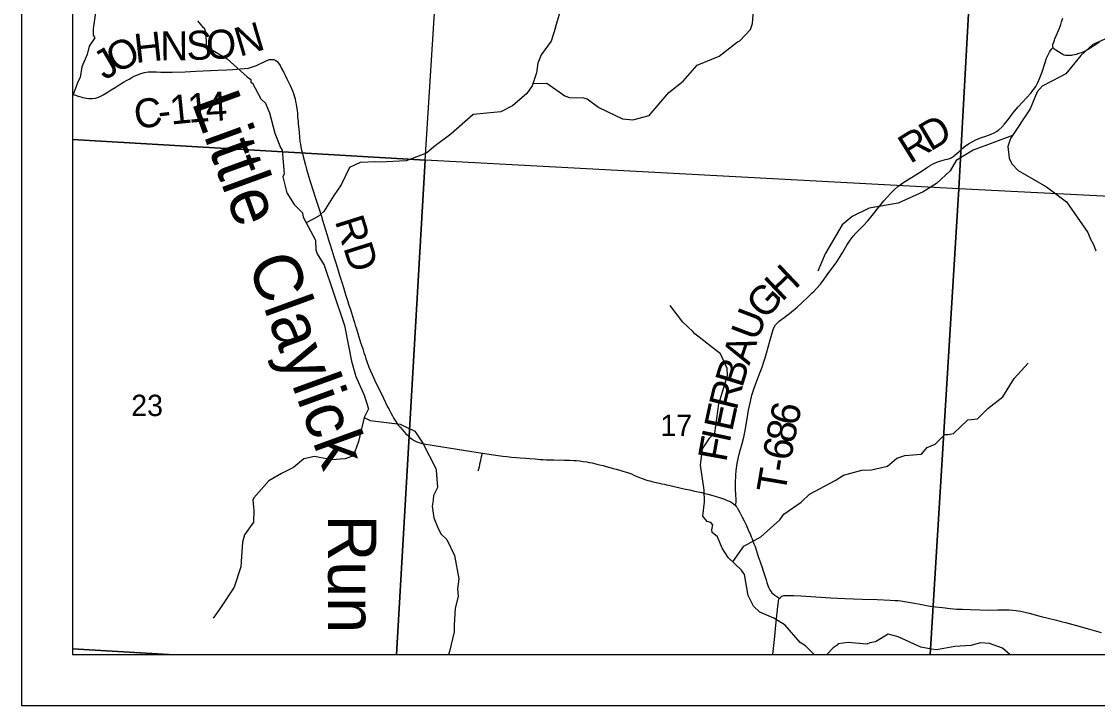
# Model space of a CAD drawing. Extents: x 0 to 34, y 0 to 22.
# Drawn here: x 2 to 4.109, y 14 to 15.341 of the extents above; entities that cross this region are included whole.
import ezdxf

# ---------------------------------------------------------------- set-up
doc = ezdxf.new("R2010")
doc.units = 0
for name, color, linetype in [('Default', 7, 'Continuous'), ('GM_X_County_Road', 7, 'Continuous'), ('GM_X_County_Road_Text', 7, 'Continuous'), ('GM_X_Minor_River', 7, 'Continuous'), ('GM_X_Minor_River_Text', 7, 'Continuous'), ('GM_X_Section', 7, 'Continuous'), ('GM_X_Section_Text', 7, 'Continuous'), ('GM_X_Township_Road', 7, 'Continuous'), ('GM_X_Township_Road_Text', 7, 'Continuous'), ('SH_Data', 7, 'Continuous'), ('SH_Text', 7, 'Continuous')]:
    doc.layers.add(name, color=color, linetype=linetype)

msp = doc.modelspace()

# ---------------------------------------------------------------- linework, layer by layer
at = {"layer": 'Default'}
for points in [[(2.1, 16.1254), (2.1, 15.1095), (2.7909, 15.0689), (2.8549, 16.0795)], [(2.1, 16.1239), (2.1, 14.1), (4.8164, 14.1), (4.8734, 15.0246), (4.8987, 15.3279), (4.9458, 15.9099), (4.9525, 15.9829), (4.6644, 15.9921), (3.9292, 16.0191), (3.6368, 16.0331), (2.1721, 16.1195)], [(2.1, 15.1095), (2.1, 14.1111), (2.2886, 14.1), (2.7351, 14.1), (2.7909, 15.0689)], [(2.7351, 14.1), (3.7808, 14.1), (3.8368, 15.0128), (2.7909, 15.0689)], [(3.7808, 14.1), (4.8257, 14.1), (4.8777, 14.9601), (3.8368, 15.0128)], [(2.1, 14.1111), (2.1, 14.1), (2.2886, 14.1)]]:
    msp.add_lwpolyline(points, close=True, dxfattribs=at)
at = {"layer": 'GM_X_County_Road'}
for points in [[(2.1, 15.1984), (2.1056, 15.1964), (2.1113, 15.1945), (2.1163, 15.1929), (2.1197, 15.192), (2.1236, 15.191), (2.1271, 15.1905), (2.1317, 15.1899), (2.1386, 15.1897), (2.1449, 15.1905), (2.1492, 15.1918), (2.1539, 15.1936), (2.16, 15.1968), (2.1677, 15.2016), (2.1756, 15.2065), (2.1835, 15.2114), (2.1915, 15.2164), (2.2001, 15.2217), (2.2058, 15.225), (2.211, 15.2279), (2.2163, 15.2309), (2.221, 15.2333), (2.2257, 15.2357), (2.2336, 15.2389), (2.2413, 15.241), (2.2485, 15.2419), (2.2546, 15.2421), (2.2645, 15.2418), (2.2732, 15.2416), (2.28, 15.2416), (2.2862, 15.2416), (2.295, 15.2417), (2.321, 15.2424), (2.3415, 15.2432), (2.385, 15.2453), (2.4024, 15.2461), (2.414, 15.2467), (2.4222, 15.2472), (2.4284, 15.2477), (2.4373, 15.2485), (2.4446, 15.2495), (2.4507, 15.2511), (2.4566, 15.2531), (2.4607, 15.2548), (2.4659, 15.2569), (2.4717, 15.2598), (2.4772, 15.2625), (2.4809, 15.2643), (2.486, 15.2661), (2.4906, 15.2666), (2.4946, 15.266), (2.4983, 15.2642), (2.5011, 15.2621), (2.5039, 15.2589), (2.5069, 15.2543), (2.5098, 15.2488), (2.5141, 15.2407), (2.5171, 15.2345), (2.5202, 15.2282), (2.5234, 15.2217), (2.5265, 15.2152), (2.5293, 15.2094), (2.5311, 15.2049), (2.5331, 15.1997), (2.5344, 15.1951), (2.5362, 15.189), (2.5372, 15.1842), (2.5384, 15.1787), (2.5391, 15.1734), (2.5401, 15.1665), (2.5406, 15.1611), (2.5412, 15.1533), (2.542, 15.1449), (2.5424, 15.1395), (2.5432, 15.1306), (2.5439, 15.1225), (2.5447, 15.1146), (2.5457, 15.1058), (2.5466, 15.1003), (2.5484, 15.0911), (2.55, 15.0844), (2.552, 15.076), (2.5539, 15.0688), (2.5565, 15.0591), (2.5587, 15.0514), (2.565, 15.0292), (2.5721, 15.0067), (2.5755, 14.9967), (2.5783, 14.9884), (2.5808, 14.9808), (2.5845, 14.9693), (2.5861, 14.9642), (2.5878, 14.9589), (2.5895, 14.9533), (2.5928, 14.9427), (2.596, 14.9322), (2.599, 14.9221), (2.6019, 14.9125), (2.6049, 14.903), (2.6082, 14.8925), (2.6124, 14.8792), (2.6153, 14.8698), (2.6193, 14.8571), (2.6235, 14.8438), (2.6279, 14.8295), (2.6311, 14.8193), (2.6353, 14.8055), (2.6389, 14.7939), (2.6417, 14.785), (2.6438, 14.7784), (2.6466, 14.7696), (2.6486, 14.7632), (2.6512, 14.7547), (2.6523, 14.751), (2.654, 14.7458), (2.6558, 14.7401), (2.6647, 14.7114), (2.6665, 14.706), (2.6688, 14.6988), (2.6712, 14.6914), (2.6732, 14.6855), (2.6751, 14.6795), (2.6763, 14.6762), (2.6777, 14.6722), (2.6795, 14.6673), (2.681, 14.6631), (2.6839, 14.6562), (2.687, 14.6487), (2.6898, 14.6428), (2.6938, 14.6341), (2.6995, 14.6224), (2.7093, 14.6022), (2.7175, 14.5855), (2.7204, 14.58), (2.7238, 14.5736), (2.727, 14.5675), (2.7298, 14.5627), (2.7324, 14.5584), (2.7358, 14.5532), (2.7378, 14.5507)], [(2.7378, 14.5507), (2.7391, 14.549), (2.742, 14.5453), (2.7464, 14.5401), (2.7497, 14.5365), (2.7535, 14.5322), (2.7562, 14.5296), (2.7609, 14.5254), (2.7655, 14.5222), (2.7698, 14.5194), (2.7749, 14.5169), (2.7785, 14.5156), (2.7833, 14.5141), (2.7918, 14.5123), (2.8008, 14.5108), (2.809, 14.5094), (2.8501, 14.5029), (2.8704, 14.4997), (2.9032, 14.4946), (2.925, 14.4914), (2.9345, 14.4899), (2.9433, 14.4888), (2.9512, 14.4878), (2.9601, 14.487), (2.9704, 14.486), (2.9775, 14.4855), (2.9892, 14.4845), (2.9964, 14.4839), (3.0067, 14.4832), (3.0156, 14.4825), (3.0223, 14.4822), (3.0292, 14.4818), (3.0346, 14.4817), (3.0432, 14.4815), (3.064, 14.481), (3.0739, 14.4808), (3.0825, 14.4803), (3.0873, 14.48), (3.0942, 14.4795), (3.1011, 14.4785), (3.1077, 14.4775), (3.1128, 14.4765), (3.1186, 14.4754), (3.1277, 14.4732), (3.133, 14.4719), (3.1398, 14.4701), (3.1456, 14.4686), (3.153, 14.4665), (3.1599, 14.4646), (3.1655, 14.4631), (3.1729, 14.461), (3.1788, 14.4594), (3.1831, 14.4582), (3.1878, 14.4566), (3.1917, 14.4552), (3.1953, 14.4538), (3.2004, 14.4517), (3.2078, 14.4485), (3.2147, 14.4457), (3.2204, 14.4437), (3.2252, 14.442), (3.2314, 14.4402), (3.2353, 14.4392), (3.2405, 14.438), (3.2472, 14.4365), (3.2522, 14.4354), (3.2552, 14.4348), (3.2599, 14.4338), (3.264, 14.4327), (3.2682, 14.4318), (3.2742, 14.4304), (3.2928, 14.4262), (3.3012, 14.4243), (3.3097, 14.4225), (3.3166, 14.4209), (3.323, 14.4195), (3.3331, 14.4172), (3.3392, 14.4158), (3.3457, 14.4142), (3.3523, 14.4125), (3.3594, 14.4105), (3.3717, 14.4065), (3.3778, 14.4043), (3.3833, 14.4021), (3.3868, 14.4005), (3.39, 14.3989), (3.393, 14.3971), (3.3955, 14.3954), (3.3978, 14.3935), (3.3991, 14.3922), (3.4009, 14.3901), (3.4026, 14.3878), (3.4041, 14.3853), (3.4071, 14.3799), (3.4127, 14.3692), (3.4161, 14.362), (3.4202, 14.3539), (3.4241, 14.3445), (3.4288, 14.3342), (3.4302, 14.3305), (3.4319, 14.3264), (3.4335, 14.3224), (3.4356, 14.3167), (3.4376, 14.3114), (3.4441, 14.2922), (3.4477, 14.2817), (3.4516, 14.2703), (3.453, 14.2662), (3.4551, 14.2597), (3.4579, 14.2503), (3.4592, 14.2461), (3.4609, 14.241), (3.463, 14.2349), (3.4642, 14.2319), (3.4652, 14.2293), (3.4668, 14.2266), (3.4679, 14.2247), (3.4693, 14.2229), (3.4707, 14.2211), (3.4731, 14.2189), (3.4767, 14.2162), (3.4846, 14.2109), (3.4858, 14.2101)], [(3.4858, 14.2101), (3.4873, 14.2119), (3.4886, 14.213), (3.4902, 14.214), (3.4921, 14.2148), (3.494, 14.2153), (3.4962, 14.2156), (3.4989, 14.2158), (3.5025, 14.2159), (3.5138, 14.2155), (3.5276, 14.2147), (3.5565, 14.2129), (3.5859, 14.2112), (3.6139, 14.2099), (3.6473, 14.2086), (3.677, 14.2077), (3.7025, 14.2067), (3.7124, 14.2061), (3.7179, 14.2058), (3.7234, 14.2052), (3.7345, 14.2035), (3.7503, 14.2006), (3.7644, 14.1978), (3.7772, 14.1956), (3.7915, 14.1936), (3.8053, 14.1919), (3.8202, 14.1902), (3.8267, 14.1896), (3.8328, 14.1891), (3.844, 14.1885), (3.8595, 14.1879), (3.8781, 14.1873), (3.8968, 14.187), (3.9135, 14.1873), (3.9257, 14.1875), (3.936, 14.1872), (3.9432, 14.1869), (3.9494, 14.1864), (3.9536, 14.1858), (3.9584, 14.1849), (3.9749, 14.181), (3.9982, 14.1747), (4.0119, 14.1713), (4.0285, 14.1672), (4.0376, 14.1649), (4.0464, 14.1625), (4.0679, 14.1565), (4.0929, 14.1495), (4.1159, 14.1431)], [(3.4727, 14.1), (3.4763, 14.1352), (3.4787, 14.1575), (3.4811, 14.1816), (3.4822, 14.1938), (3.4834, 14.2034), (3.4839, 14.2057), (3.4844, 14.2075), (3.4852, 14.2092), (3.4858, 14.2101)]]:
    msp.add_lwpolyline(points, dxfattribs=at)
at = {"layer": 'GM_X_Minor_River'}
for points in [[(3.4329, 15.3367), (3.4351, 15.3702), (3.4525, 15.3942), (3.4647, 15.4288), (3.4749, 15.4801), (3.467, 15.5204), (3.4651, 15.5505), (3.4856, 15.5893), (3.4901, 15.6049), (3.4909, 15.6269), (3.4973, 15.6326), (3.5072, 15.6528), (3.5068, 15.6916), (3.4936, 15.7687), (3.4876, 15.8007)], [(3.0463, 15.3291), (3.0628, 15.3843)], [(2.1467, 15.3721), (2.1404, 15.3265), (2.1404, 15.314), (2.1435, 15.309), (2.1329, 15.2923), (2.1287, 15.2759), (2.1182, 15.2519), (2.1148, 15.2307), (2.111, 15.2238), (2.1, 15.1941)], [(2.3448, 15.3418), (2.3547, 15.3301), (2.3581, 15.3282), (2.3612, 15.3183), (2.3616, 15.2944), (2.3676, 15.2883), (2.4032, 15.2675), (2.4425, 15.2322), (2.4493, 15.2269), (2.4493, 15.222), (2.4528, 15.2201), (2.469, 15.1893), (2.4781, 15.1806), (2.4842, 15.1662), (2.4861, 15.1616), (2.4963, 15.1217), (2.5077, 15.0936), (2.5111, 15.0883), (2.5145, 15.042), (2.5119, 15.0363), (2.5145, 15.026), (2.5202, 15.0051), (2.5346, 14.9823), (2.5505, 14.9657), (2.552, 14.9573), (2.5759, 14.9121), (2.5767, 14.8931), (2.5793, 14.8851), (2.593, 14.8631), (2.6111, 14.8107), (2.6331, 14.7446), (2.6468, 14.6751), (2.6552, 14.6447), (2.6718, 14.6083), (2.6802, 14.5817), (2.6715, 14.5642), (2.6832, 14.5585), (2.7422, 14.5514), (2.7706, 14.5378), (2.7864, 14.5143), (2.8118, 14.4645), (2.8126, 14.4615), (2.8156, 14.4273), (2.8077, 14.4113), (2.8066, 14.4026), (2.8047, 14.3908), (2.8081, 14.368), (2.8169, 14.3471), (2.8225, 14.3357), (2.8339, 14.3255), (2.8487, 14.294), (2.857, 14.2484), (2.8544, 14.2286), (2.8559, 14.2138), (2.8499, 14.191), (2.8477, 14.1575), (2.848, 14.1548), (2.848, 14.1446), (2.8386, 14.1058), (2.8368, 14.1)], [(3.0023, 15.219), (3.0293, 15.2199), (3.0649, 15.1949), (3.0738, 15.1919), (3.1014, 15.1914), (3.1085, 15.1893), (3.1315, 15.1722), (3.1777, 15.1499), (3.198, 15.1477), (3.2304, 15.1565), (3.2684, 15.2013), (3.2967, 15.2239), (3.3241, 15.2553), (3.3673, 15.2725), (3.4034, 15.301), (3.408, 15.3031), (3.4287, 15.3249), (3.4329, 15.3368)], [(4.1959, 15.3376), (4.1676, 15.326), (4.0999, 15.2957), (4.0761, 15.2743), (4.0471, 15.2385), (4.0354, 15.2323), (4.0002, 15.2143), (3.9908, 15.2032), (3.9769, 15.1698), (3.9382, 15.1115), (3.933, 15.0955), (3.9354, 15.0727), (3.9408, 15.0617), (3.9534, 15.0489), (4.0086, 15.0165), (4.0479, 14.9871), (4.0896, 14.9273), (4.095, 14.9144), (4.1008, 14.9038), (4.1058, 14.8913)], [(3.0463, 15.3291), (3.0383, 15.3024), (3.0185, 15.2753), (3.012, 15.2588), (3.0092, 15.2399), (3.0008, 15.2144), (2.9902, 15.1995), (2.9622, 15.1753), (2.9396, 15.1639), (2.9255, 15.1621), (2.8853, 15.1584), (2.8415, 15.1196), (2.8082, 15.0948), (2.7938, 15.0824), (2.7537, 15.0677), (2.7022, 15.0648), (2.6943, 15.0654), (2.664, 15.0645), (2.6426, 15.0545), (2.6264, 15.0205), (2.6122, 14.9997), (2.5927, 14.9684), (2.5811, 14.9585), (2.5577, 14.9464)], [(3.9422, 15.1175), (3.8651, 15.0883), (3.8318, 15.068), (3.8202, 15.0478), (3.793, 15.023), (3.7673, 15.0069), (3.7181, 14.9846), (3.6616, 14.9749), (3.6283, 14.9584), (3.6083, 14.9419), (3.5752, 14.8856), (3.561, 14.8513)], [(3.5535, 14.1), (3.5364, 14.1169), (3.526, 14.1233), (3.4965, 14.1577), (3.4746, 14.1709), (3.4473, 14.1832), (3.4348, 14.1946), (3.4241, 14.2158), (3.4167, 14.2567), (3.4113, 14.2652), (3.3848, 14.2904), (3.3729, 14.3086), (3.3641, 14.3305), (3.3538, 14.3392), (3.3528, 14.3445), (3.355, 14.3543), (3.351, 14.359), (3.3435, 14.3604), (3.3351, 14.3709), (3.3386, 14.3989), (3.3378, 14.4221), (3.331, 14.4713), (3.3346, 14.5031), (3.3492, 14.5246), (3.3586, 14.5338), (3.3667, 14.5913), (3.3835, 14.6466), (3.3828, 14.6607), (3.3701, 14.6892), (3.3199, 14.7284), (3.3155, 14.7331), (3.296, 14.7515), (3.2716, 14.7838)], [(3.3944, 14.2813), (3.4157, 14.3121), (3.4488, 14.3308), (3.4861, 14.3638), (3.4944, 14.375), (3.5283, 14.3986), (3.5447, 14.4144), (3.5946, 14.4412), (3.6112, 14.4517), (3.6467, 14.4616), (3.666, 14.4621), (3.6975, 14.4691), (3.7158, 14.4845), (3.7314, 14.4897), (3.764, 14.4924), (3.775, 14.5057), (3.7907, 14.5121), (3.8094, 14.5312), (3.8162, 14.5314), (3.8269, 14.5329), (3.8549, 14.5598), (3.8739, 14.5618), (3.8938, 14.5824), (3.9232, 14.605), (3.9458, 14.6412), (3.9728, 14.6711)], [(2.6715, 14.5642), (2.6603, 14.5174), (2.6541, 14.499), (2.6466, 14.4882), (2.6343, 14.4833), (2.6078, 14.4815), (2.574, 14.4882), (2.5531, 14.4836), (2.5333, 14.4668), (2.5095, 14.455), (2.4848, 14.4402), (2.4551, 14.4073), (2.4531, 14.4025), (2.4551, 14.3819), (2.4544, 14.3595), (2.437, 14.3346), (2.4328, 14.32), (2.4305, 14.2824), (2.4298, 14.2718), (2.4169, 14.232), (2.39, 14.1911), (2.3758, 14.171)], [(3.9373, 14.1), (3.9224, 14.1125), (3.8971, 14.1216), (3.8793, 14.1227), (3.8608, 14.1177), (3.8294, 14.1153), (3.7935, 14.1088), (3.7837, 14.1103), (3.7629, 14.1144), (3.7183, 14.1345), (3.6986, 14.1401), (3.6737, 14.1245), (3.6627, 14.1225), (3.657, 14.1199), (3.6204, 14.1232), (3.6007, 14.1209), (3.5984, 14.1182), (3.5905, 14.1133), (3.5785, 14.1)]]:
    msp.add_lwpolyline(points, dxfattribs=at)
at = {"layer": 'GM_X_Section'}
for points in [[(2.8549, 16.0795), (3.8924, 16.0203), (3.8368, 15.0128), (2.7909, 15.0689)], [(3.8924, 16.0203), (4.9447, 15.9846), (4.9568, 15.9843), (4.8777, 14.9601), (3.8368, 15.0128)]]:
    msp.add_lwpolyline(points, close=True, dxfattribs=at)
at = {"layer": 'GM_X_Township_Road'}
for points in [[(4.1125, 15.3002), (4.0925, 15.2869), (4.0848, 15.2828), (4.0773, 15.2796), (4.0723, 15.278), (4.0673, 15.2763), (4.0636, 15.2754), (4.0606, 15.2747), (4.0576, 15.2742), (4.0544, 15.2738), (4.0494, 15.2738), (4.0462, 15.2743), (4.0437, 15.2749), (4.0409, 15.2761), (4.027, 15.2845), (4.0249, 15.286), (4.0233, 15.2874), (4.0224, 15.2885), (4.0218, 15.2896), (4.0213, 15.2911), (4.0213, 15.293), (4.0214, 15.2949), (4.0216, 15.2967), (4.0223, 15.2986), (4.0245, 15.3042), (4.0255, 15.3067), (4.0281, 15.3126), (4.0307, 15.3187), (4.0341, 15.3278), (4.0367, 15.3349), (4.0385, 15.3404), (4.0408, 15.3473)], [(3.3991, 14.3922), (3.4003, 14.3956), (3.4007, 14.3978), (3.4009, 14.4001), (3.4009, 14.4028), (3.3993, 14.4241), (3.3991, 14.4301), (3.3992, 14.4361), (3.4001, 14.4515), (3.4009, 14.4607), (3.4027, 14.4742), (3.405, 14.487), (3.4076, 14.4978), (3.4121, 14.5133), (3.4155, 14.526), (3.4181, 14.5388), (3.4223, 14.562), (3.4251, 14.5786), (3.4287, 14.5962), (3.4316, 14.6083), (3.4351, 14.6201), (3.4389, 14.6312), (3.4478, 14.6536), (3.4515, 14.6635), (3.455, 14.6735), (3.4576, 14.6818), (3.4602, 14.6907), (3.4635, 14.7027), (3.4666, 14.714), (3.4703, 14.7278), (3.4732, 14.7367), (3.4754, 14.7417), (3.478, 14.7459), (3.4815, 14.7501), (3.4851, 14.7535), (3.4976, 14.7626), (3.5054, 14.7687), (3.5202, 14.7811), (3.5308, 14.7907), (3.5407, 14.8), (3.5496, 14.8086), (3.553, 14.8118), (3.5582, 14.8171), (3.5658, 14.826), (3.573, 14.8354), (3.5791, 14.8441), (3.5865, 14.8541), (3.5906, 14.8596), (3.598, 14.8696), (3.6015, 14.8747), (3.6048, 14.88), (3.6098, 14.8886), (3.6178, 14.9026), (3.6243, 14.9124), (3.6298, 14.9199), (3.6351, 14.9259), (3.6494, 14.9404), (3.6588, 14.9503), (3.6673, 14.9602), (3.6823, 14.9792), (3.6904, 14.9893), (3.6973, 14.9973), (3.7032, 15.0036), (3.7111, 15.0115), (3.7175, 15.0174), (3.7218, 15.0208), (3.7274, 15.0247), (3.7495, 15.0382), (3.7652, 15.0482), (3.7734, 15.0537), (3.7796, 15.0577), (3.7866, 15.0616), (3.7939, 15.0649), (3.8021, 15.0678), (3.811, 15.0701), (3.8177, 15.0718), (3.8218, 15.0736), (3.826, 15.0762), (3.829, 15.0785), (3.8332, 15.082), (3.837, 15.0855), (3.8437, 15.0915), (3.8498, 15.0964), (3.8563, 15.1009), (3.8631, 15.1051), (3.8702, 15.1088), (3.8794, 15.1125), (3.8899, 15.1163), (3.9004, 15.1199), (3.9062, 15.1224), (3.911, 15.1252), (3.9156, 15.1284), (3.9211, 15.1334), (3.9265, 15.1394), (3.9342, 15.1491), (3.9432, 15.1609), (3.9535, 15.1733), (3.9627, 15.1833), (3.9699, 15.191), (3.9782, 15.2003), (3.9836, 15.2072), (3.9877, 15.2134), (3.9919, 15.2211), (3.9959, 15.2302), (4.0004, 15.2418), (4.0061, 15.2602), (4.0091, 15.269), (4.0125, 15.2769), (4.0145, 15.2806), (4.0166, 15.2842), (4.0193, 15.2873), (4.0218, 15.2896)], [(2.8953, 14.4597), (2.8973, 14.4676), (2.8981, 14.4715), (2.8992, 14.4764), (2.8999, 14.48), (2.9009, 14.4843), (2.9018, 14.4882), (2.9032, 14.4946)]]:
    msp.add_lwpolyline(points, dxfattribs=at)
at = {"layer": 'SH_Data'}
for p, q in [((2, 21), (2, 14)), ((2.1, 20.9), (2.1, 14.1)), ((2.1, 14.1), (8.9, 14.1)), ((2.1, 14.1), (2.1, 14.1)), ((2, 14), (9, 14))]:
    msp.add_line(p, q, dxfattribs=at)
at = {"layer": 'SH_Text'}
msp.add_lwpolyline([(2.1, 20.9), (2.1, 14.1), (8.0885, 14.1)], dxfattribs=at)

# ---------------------------------------------------------------- texts
at = {"layer": 'GM_X_County_Road_Text'}
for s, height, rotation, p in [('N', 0.0568, 16.5268, (2.4276, 15.2714)), ('H', 0.0568, 6.267, (2.2239, 15.2592)), ('N', 0.0568, 0.3752, (2.2721, 15.2646)), ('S', 0.0568, 2.2013, (2.3241, 15.265)), ('O', 0.0568, 2.752, (2.363, 15.2665)), ('J', 0.0568, 30.3125, (2.1625, 15.2247)), ('O', 0.0568, 27.4823, (2.1849, 15.2378)), ('C', 0.0568, 7.1216, (2.224, 15.1301)), ('1', 0.0568, 5.7209, (2.2931, 15.1386)), ('1', 0.0568, 4.7515, (2.3277, 15.1421)), ('4', 0.0568, 3.3897, (2.3622, 15.1449)), ('-', 0.0568, 6.6893, (2.2702, 15.1359)), ('RD', 0.05682, 287.5008, (2.6138, 14.9498))]:
    msp.add_text(s, height=height, rotation=rotation, dxfattribs=at).set_placement(p)
at = {"layer": 'GM_X_Minor_River_Text'}
for s, rotation, p in [('Little', 289.9986, (2.3329, 15.1833)), ('Claylick', 289.9986, (2.4426, 14.8677)), ('Run', 269.9991, (2.601, 14.3742))]:
    msp.add_text(s, height=0.0947, rotation=rotation, dxfattribs=at).set_placement(p)
at = {"layer": 'GM_X_Section_Text'}
for s, p in [('23', (2.215, 14.5673)), ('17', (3.2521, 14.5282))]:
    msp.add_text(s, height=0.04186, rotation=0, dxfattribs=at).set_placement(p)
at = {"layer": 'GM_X_Township_Road_Text'}
for s, rotation, p in [('D', 30.5858, (3.7811, 15.0854)), ('R', 31.935, (3.7418, 15.0609)), ('H', 43.4942, (3.4902, 14.7902)), ('G', 47.346, (3.457, 14.7542)), ('U', 69.0963, (3.4421, 14.7123)), ('A', 71.307, (3.4263, 14.6655)), ('B', 72.6895, (3.4125, 14.6213)), ('R', 76.1223, (3.4016, 14.5768)), ('E', 77.7836, (3.3927, 14.5357)), ('6', 78.0221, (3.521, 14.5463)), ('8', 78.5482, (3.514, 14.5122)), ('I', 77.9606, (3.3878, 14.513)), ('F', 79.6956, (3.3811, 14.4757)), ('6', 79.2004, (3.5075, 14.4779)), ('T', 80.3939, (3.4964, 14.4134)), ('-', 79.9493, (3.5035, 14.4552))]:
    msp.add_text(s, height=0.0568, rotation=rotation, dxfattribs=at).set_placement(p)

doc.saveas('drawing.dxf')
